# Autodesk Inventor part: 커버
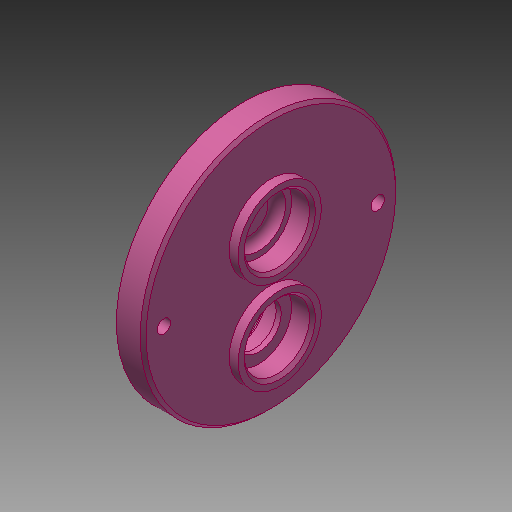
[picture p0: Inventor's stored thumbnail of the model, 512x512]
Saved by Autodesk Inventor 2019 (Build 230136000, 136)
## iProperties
Created: 2016-02
Part Number: 커버
Material: 알루미늄 6061
Document SubType Name: Modeling
Designer: mduedu
Density: 2.71 g/cm^3
Appearance: 분홍색
Author: mduedu
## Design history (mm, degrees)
sketch "스케치1"
  geometry: C1 r 43 at (0, 0); 1 further point
  constraints: 1 centre point, 1 coincident
  dimensions: "d0" = 86 diameter of C1
extrude "돌출1" new body sketch "스케치1" distance "d1" = 9; taper "d2" = 0 deg
sketch "스케치2"
  geometry: C1 r 14 at (0, 11); 1 further point
  constraints: 1 centre point, 1 vertical alignment
  dimensions: "d3" = 28 diameter of C1; "d6" = 11 distance of C1.centre point (0, 0)
extrude "돌출2" join sketch "스케치2" distance "d7" = 3; taper "d8" = 0 deg
sketch "스케치3"
  geometry: C1 r 14 at (0, -20); 1 further point
  constraints: 1 centre point, 1 vertical alignment
  dimensions: "d9" = 28 diameter of C1; "d10" = 20 distance of C1.centre point (0, 0)
extrude "돌출3" join sketch "스케치3" distance "d11" = 3; taper "d12" = 0 deg
hole "구멍1" diameter "d15" = 22; stored, may be unused: countersink angle "d19" = 90 deg, drill point angle "d21" = 0 deg; dims "d13" = 10, "d14" = 10, "d16" = 6, "d17" = 4, "d18" = 2, "d20" = 7
hole "구멍2" diameter "d24" = 18; stored, may be unused: countersink angle "d28" = 90 deg, drill point angle "d30" = 0 deg; dims "d25" = 6, "d26" = 4, "d27" = 2, "d29" = 3, "d95" = 10, "d96" = 10
fillet "모깎기7" dims "d97" = 3
hole "구멍3" diameter "d33" = 22; stored, may be unused: countersink angle "d37" = 90 deg, drill point angle "d39" = 0 deg; dims "d34" = 6, "d35" = 4, "d36" = 2, "d38" = 7, "d73" = 10, "d74" = 10
sketch "스케치4"
  geometry: C1 r 14 at (0, -20) reference; C2 r 18 at (0, -20); 1 further point
  constraints: 1 centre point, 1 coincident
  dimensions: "d40" = 36 diameter of C2
extrude "돌출4" join sketch "스케치4" distance "d41" = 4; taper "d42" = 0 deg
hole "구멍4" diameter "d45" = 22; stored, may be unused: countersink angle "d49" = 90 deg, drill point angle "d51" = 0 deg; dims "d46" = 6, "d47" = 4, "d48" = 2, "d50" = 7.3, "d98" = 10, "d99" = 10
hole "구멍5" diameter "d54" = 15; stored, may be unused: countersink angle "d58" = 90 deg, drill point angle "d60" = 0 deg; dims "d52" = 10, "d53" = 10, "d55" = 6, "d56" = 4, "d57" = 2, "d59" = 7
chamfer "모따기1" distance "d63" = 1; stored, may be unused: second distance "d64" = 2, angle "d65" = 45 deg
chamfer "모따기3" distance "d100" = 0.7; stored, may be unused: second distance "d101" = 2, angle "d102" = 30 deg
sketch "스케치5" dims "d67" = 72
  geometry: 4 further points
  constraints: 2 horizontal alignment, 1 coincident, 5 other
  dimensions: "d71" = 360 deg dimension on point (0, 0) point (-36, 0) (derived)
sketch "스케치6"
  geometry: 2 further points
hole "구멍6" sketch "스케치6" at (-36, 0), (36, 0) diameter "d76" = 4.5; stored, may be unused: countersink angle "d80" = 90 deg, drill point angle "d82" = 0 deg; dims "d77" = 6, "d78" = 8, "d79" = 4.6, "d81" = 8
chamfer "모따기2" distance "d90" = 1; stored, may be unused: second distance "d91" = 2, angle "d92" = 45 deg
node "솔리드1"
